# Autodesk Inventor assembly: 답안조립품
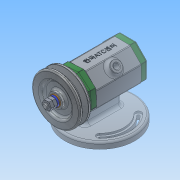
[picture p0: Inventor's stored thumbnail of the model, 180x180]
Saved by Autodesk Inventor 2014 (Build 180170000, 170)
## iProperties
Created: 2017-06
Part Number: 답안조립품
Document SubType Name: Assembly
Designer: NET
Author: NET
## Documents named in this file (13)
- C:\Users\NET\Desktop\470607V1019\답안조립품.iam
- C:\Users\NET\Desktop\470607V1019\답안본체.ipt
- C:\Users\NET\Desktop\470607V1019\축.ipt
- C:\Users\NET\Desktop\470607V1019\베어링 15 x 32 x 9.ipt
- C:\Users\NET\Desktop\470607V1019\뒤커버.ipt
- C:\Users\NET\Desktop\470607V1019\앞커버.ipt
- C:\Users\NET\Desktop\470607V1019\오일 실 15 25 7.ipt
- C:\Users\NET\Desktop\470607V1019\키 3 x 3 x 12.ipt
- C:\Users\NET\Desktop\470607V1019\V벨트풀리.ipt
- C:\Users\NET\Desktop\470607V1019\너트 M 8.ipt
- C:\Users\NET\Desktop\470607V1019\스프링와셔 8.ipt
- C:\Users\NET\Desktop\470607V1019\와셔 8x17.ipt
- C:\Users\NET\Desktop\470607V1019\볼트 M4 x 12.ipt
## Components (1 placed, 1 different names)
1. V벨트풀리:1
